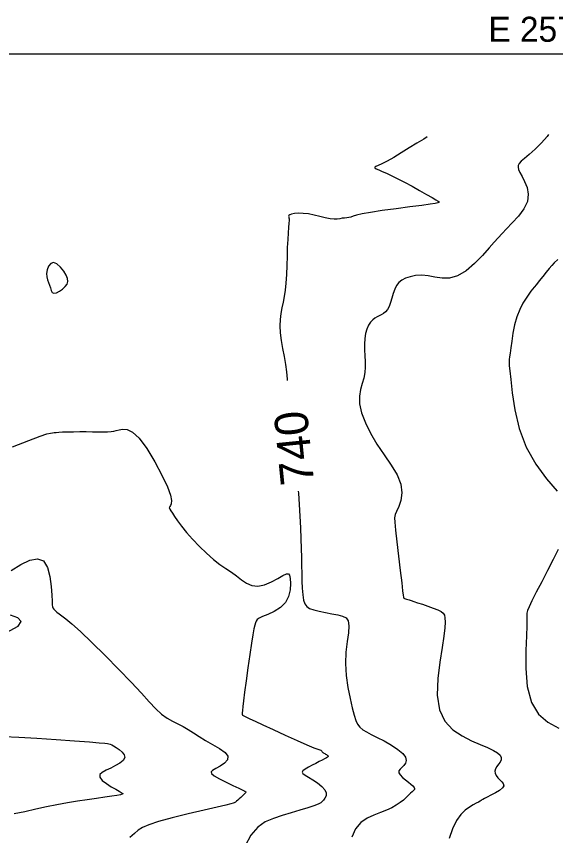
# Model space of a CAD drawing. Extents: x 2566142 to 2571431, y 418755 to 421584.
# Drawn here: x 2569642.8 to 2569965.9, y 421093.3 to 421584.4 of the extents above; entities that cross this region are included whole.
import ezdxf

# ---------------------------------------------------------------- set-up
doc = ezdxf.new("R2010")
doc.units = 0
for name, color, linetype in [('Contour_ADS_Label_Major', 7, 'Continuous'), ('Contour_ADS_Major', 7, 'Continuous'), ('Contour_ADS_Minor', 7, 'Continuous'), ('Contour_ADS_State_Plane_Border', 7, 'Continuous')]:
    doc.layers.add(name, color=color, linetype=linetype)

msp = doc.modelspace()

# ---------------------------------------------------------------- linework, layer by layer
at = {"layer": 'Contour_ADS_Major'}
for points in [[(2569889.03, 421512.21), (2569886.89, 421510.88), (2569882.78, 421508.41), (2569878.19, 421505.58), (2569873.45, 421502.62), (2569868.91, 421499.85), (2569864.93, 421497.56), (2569861.8, 421495.98), (2569859.54, 421494.98), (2569858.12, 421494.37), (2569857.49, 421493.95), (2569857.62, 421493.52), (2569858.45, 421493.01), (2569859.93, 421492.35), (2569862, 421491.47), (2569864.61, 421490.31), (2569867.74, 421488.85), (2569871.35, 421487.08), (2569875.43, 421484.97), (2569879.88, 421482.55), (2569884.36, 421480.04), (2569888.49, 421477.69), (2569891.87, 421475.77), (2569894.2, 421474.45), (2569895.55, 421473.65), (2569896.1, 421473.18), (2569896.01, 421472.88), (2569895.35, 421472.6), (2569893.74, 421472.24), (2569890.69, 421471.76), (2569885.73, 421471.07), (2569878.64, 421470.15), (2569870.35, 421469.08), (2569862.04, 421467.95), (2569854.92, 421466.88), (2569849.89, 421465.94), (2569846.66, 421465.16), (2569844.63, 421464.55), (2569843.23, 421464.11), (2569841.96, 421463.83), (2569840.7, 421463.66), (2569839.42, 421463.52), (2569838.09, 421463.35), (2569836.67, 421463.1), (2569835.06, 421462.88), (2569833.14, 421462.82), (2569830.78, 421463.05), (2569827.91, 421463.65), (2569824.68, 421464.47), (2569821.27, 421465.32), (2569817.87, 421465.99), (2569814.66, 421466.32), (2569811.79, 421466.36), (2569809.39, 421466.17), (2569807.61, 421465.85), (2569806.54, 421465.46), (2569806.03, 421465.03), (2569805.91, 421464.58), (2569805.99, 421464.15), (2569806.1, 421463.7), (2569806.18, 421463.07), (2569806.2, 421462.04), (2569806.13, 421460.37), (2569805.93, 421457.9), (2569805.66, 421454.63), (2569805.37, 421450.62), (2569805.12, 421445.92), (2569804.95, 421440.64), (2569804.8, 421435.07), (2569804.61, 421429.59), (2569804.31, 421424.55), (2569803.84, 421420.21), (2569803.25, 421416.44), (2569802.59, 421413.02), (2569801.93, 421409.72), (2569801.34, 421406.34), (2569800.9, 421402.78), (2569800.72, 421398.93), (2569800.9, 421394.73), (2569801.48, 421390.13), (2569802.33, 421385.29), (2569803.26, 421380.42), (2569804.08, 421375.71), (2569804.66, 421371.28), (2569805.05, 421366.93), (2569805.11, 421366.09)], [(2569811.67, 421299.75), (2569811.77, 421298.66), (2569812.25, 421291.83), (2569812.64, 421284.77), (2569812.95, 421277.8), (2569813.19, 421271.26), (2569813.39, 421265.39), (2569813.55, 421260.09), (2569813.69, 421255.19), (2569813.8, 421250.49), (2569813.9, 421245.89), (2569814.06, 421241.55), (2569814.34, 421237.68), (2569814.82, 421234.52), (2569815.57, 421232.22), (2569816.74, 421230.63), (2569818.48, 421229.51), (2569820.97, 421228.65), (2569824.25, 421227.85), (2569828.02, 421227.07), (2569831.87, 421226.33), (2569835.39, 421225.61), (2569838.23, 421224.87), (2569840.31, 421223.78), (2569841.59, 421222), (2569842.05, 421219.13), (2569841.73, 421214.93), (2569840.99, 421209.57), (2569840.26, 421203.3), (2569839.96, 421196.42), (2569840.4, 421189.21), (2569841.41, 421182.1), (2569842.72, 421175.52), (2569844.02, 421169.9), (2569845.12, 421165.57), (2569846.12, 421162.37), (2569847.19, 421160.01), (2569848.53, 421158.24), (2569850.29, 421156.77), (2569852.57, 421155.4), (2569855.44, 421153.94), (2569858.97, 421152.19), (2569863.13, 421150.02), (2569867.46, 421147.55), (2569871.4, 421144.99), (2569874.38, 421142.52), (2569875.99, 421140.31), (2569876.41, 421138.37), (2569875.97, 421136.71), (2569874.99, 421135.32), (2569873.8, 421134.17), (2569872.7, 421133.15), (2569871.98, 421132.13), (2569871.91, 421131), (2569872.71, 421129.66), (2569874.14, 421128.18), (2569875.89, 421126.69), (2569877.66, 421125.29), (2569879.16, 421124.08), (2569880.32, 421123.06), (2569881.08, 421122.21), (2569881.42, 421121.5), (2569881.3, 421120.89), (2569880.79, 421120.3), (2569879.97, 421119.61), (2569878.94, 421118.72), (2569877.75, 421117.55), (2569876.36, 421116.15), (2569874.71, 421114.61), (2569872.75, 421113.03), (2569870.41, 421111.48), (2569867.68, 421109.96), (2569864.54, 421108.49), (2569860.98, 421107.05), (2569857.05, 421105.58), (2569853.03, 421103.76), (2569849.25, 421101.18), (2569846.06, 421097.44), (2569843.7, 421092.31)]]:
    msp.add_lwpolyline(points, dxfattribs=at)
msp.add_lwpolyline([(2569665.27, 421418.4), (2569666.79, 421418.67), (2569668.63, 421419.58), (2569670.48, 421420.9), (2569672.06, 421422.4), (2569673.13, 421423.9), (2569673.62, 421425.46), (2569673.47, 421427.23), (2569672.64, 421429.31), (2569671.15, 421431.74), (2569669.22, 421434.13), (2569667.1, 421435.97), (2569665.07, 421436.78), (2569663.35, 421436.23), (2569662.03, 421434.63), (2569661.16, 421432.45), (2569660.79, 421430.18), (2569660.93, 421428.18), (2569661.42, 421426.45), (2569662.08, 421424.84), (2569662.71, 421423.24), (2569663.18, 421421.59), (2569663.62, 421420.06), (2569664.25, 421418.92), (2569665.27, 421418.4)], close=True, dxfattribs=at)
at = {"layer": 'Contour_ADS_Minor'}
for points in [[(2569961.65, 421513.59), (2569960.9, 421512.41), (2569957.45, 421508.56), (2569953.58, 421504.86), (2569949.98, 421501.68), (2569947.22, 421499.29), (2569945.3, 421497.55), (2569944.11, 421496.23), (2569943.51, 421495.09), (2569943.4, 421493.91), (2569943.75, 421492.51), (2569944.54, 421490.73), (2569945.78, 421488.4), (2569947.35, 421485.4), (2569948.79, 421481.82), (2569949.53, 421477.8), (2569949.03, 421473.49), (2569946.91, 421469.03), (2569943.66, 421464.66), (2569939.96, 421460.6), (2569936.51, 421457.1), (2569933.79, 421454.26), (2569931.49, 421451.72), (2569929.09, 421448.99), (2569926.09, 421445.55), (2569922.11, 421441.13), (2569917.39, 421436.33), (2569912.28, 421431.94), (2569907.17, 421428.79), (2569902.36, 421427.42), (2569897.85, 421427.43), (2569893.6, 421428.15), (2569889.55, 421428.91), (2569885.66, 421429.2), (2569882.03, 421428.97), (2569878.77, 421428.33), (2569875.97, 421427.39), (2569873.73, 421426.23), (2569871.97, 421424.8), (2569870.59, 421423.03), (2569869.49, 421420.88), (2569868.58, 421418.31), (2569867.76, 421415.55), (2569866.96, 421412.84), (2569866.08, 421410.46), (2569865.07, 421408.6), (2569863.94, 421407.22), (2569862.73, 421406.2), (2569861.46, 421405.46), (2569860.18, 421404.87), (2569858.89, 421404.29), (2569857.58, 421403.57), (2569856.28, 421402.55), (2569854.98, 421401.12), (2569853.77, 421399.25), (2569852.75, 421396.97), (2569851.99, 421394.28), (2569851.56, 421391.23), (2569851.41, 421387.92), (2569851.44, 421384.46), (2569851.58, 421380.97), (2569851.71, 421377.55), (2569851.74, 421374.2), (2569851.53, 421370.9), (2569850.96, 421367.61), (2569850, 421364.3), (2569848.98, 421360.76), (2569848.31, 421356.8), (2569848.43, 421352.2), (2569849.64, 421346.82), (2569851.89, 421340.83), (2569855.01, 421334.47), (2569858.83, 421327.99), (2569863.12, 421321.6), (2569867.34, 421315.4), (2569870.9, 421309.48), (2569873.19, 421303.91), (2569873.82, 421298.79), (2569873.2, 421294.26), (2569871.92, 421290.5), (2569870.6, 421287.66), (2569869.74, 421285.71), (2569869.39, 421283.86), (2569869.49, 421281.12), (2569870, 421276.48), (2569870.82, 421269.35), (2569871.82, 421260.77), (2569872.82, 421252.14), (2569873.66, 421244.88), (2569874.21, 421240.08), (2569874.54, 421237.39), (2569874.78, 421236.16), (2569875.04, 421235.7), (2569875.42, 421235.44), (2569875.93, 421235.25), (2569876.57, 421235.07), (2569877.31, 421234.86), (2569878.19, 421234.59), (2569879.34, 421234.2), (2569880.94, 421233.65), (2569883.15, 421232.9)], [(2569967.18, 421438.64), (2569965.12, 421436.63), (2569963.6, 421435.02), (2569962.1, 421433.29), (2569960.25, 421431.04), (2569958.17, 421428.47), (2569956.13, 421425.93), (2569954.37, 421423.75), (2569953.08, 421422.15), (2569952.07, 421420.89), (2569951.08, 421419.59), (2569949.85, 421417.9), (2569948.21, 421415.5), (2569946.3, 421412.39), (2569944.36, 421408.63), (2569942.62, 421404.28), (2569941.28, 421399.45), (2569940.3, 421394.48), (2569939.58, 421389.77), (2569939.06, 421385.7), (2569938.65, 421382.59), (2569938.35, 421380.32), (2569938.14, 421378.7), (2569938.02, 421377.55), (2569938.01, 421376.56), (2569938.14, 421374.99), (2569938.46, 421372), (2569939.01, 421366.73), (2569939.91, 421358.66), (2569941.49, 421348.52), (2569944.14, 421337.35), (2569948.25, 421326.21), (2569953.98, 421315.99), (2569960.53, 421307.07), (2569966.86, 421299.67)], [(2569640.37, 421326.26), (2569650.3, 421330.17), (2569657.04, 421332.7), (2569661.02, 421334.04), (2569663.16, 421334.6), (2569664.37, 421334.77), (2569665.43, 421334.89), (2569666.66, 421335.02), (2569668.28, 421335.15), (2569670.49, 421335.26), (2569673.42, 421335.35), (2569676.91, 421335.41), (2569680.71, 421335.45), (2569684.6, 421335.44), (2569688.35, 421335.41), (2569691.83, 421335.37), (2569694.92, 421335.36), (2569697.48, 421335.4), (2569699.48, 421335.52), (2569701.11, 421335.74), (2569702.64, 421336.07), (2569704.34, 421336.51), (2569706.44, 421336.94), (2569709.07, 421336.76), (2569712.31, 421335.19), (2569716.26, 421331.49), (2569720.88, 421325.26), (2569725.67, 421317.45), (2569730.02, 421309.36), (2569733.32, 421302.31), (2569735.12, 421297.28), (2569735.71, 421294.09), (2569735.54, 421292.22), (2569735.09, 421291.18), (2569734.72, 421290.54), (2569734.51, 421290.13), (2569734.42, 421289.87), (2569734.44, 421289.64), (2569734.55, 421289.37), (2569734.82, 421288.88), (2569735.36, 421288.03), (2569736.24, 421286.65), (2569737.56, 421284.62), (2569739.38, 421281.96), (2569741.76, 421278.74), (2569744.76, 421275.03), (2569748.39, 421270.92), (2569752.44, 421266.66), (2569756.67, 421262.55), (2569760.82, 421258.89), (2569764.69, 421255.88), (2569768.27, 421253.37), (2569771.6, 421251.14), (2569774.74, 421248.95), (2569777.74, 421246.69), (2569780.75, 421244.64), (2569783.95, 421243.21), (2569787.51, 421242.81), (2569791.5, 421243.67), (2569795.6, 421245.39), (2569799.41, 421247.41), (2569802.5, 421249.16), (2569804.59, 421250.16), (2569805.83, 421250.25), (2569806.47, 421249.35), (2569806.79, 421247.37), (2569806.96, 421244.32), (2569806.76, 421240.59), (2569805.87, 421236.66), (2569803.99, 421233.01), (2569800.96, 421230.01), (2569797.25, 421227.66), (2569793.5, 421225.87), (2569790.35, 421224.54), (2569788.27, 421223.56), (2569787.09, 421222.75), (2569786.48, 421221.92), (2569786.11, 421220.89), (2569785.69, 421219.42), (2569785.16, 421217.16), (2569784.48, 421213.69), (2569783.63, 421208.63), (2569782.6, 421201.79), (2569781.5, 421193.95), (2569780.45, 421186.1), (2569779.55, 421179.23)], [(2569967.39, 421264.86), (2569964.48, 421258.77), (2569961.1, 421252.11), (2569957.58, 421245.37), (2569954.32, 421239.16), (2569951.69, 421234.04), (2569949.99, 421230.46), (2569949.07, 421228.14), (2569948.71, 421226.68), (2569948.65, 421225.64), (2569948.68, 421224.55), (2569948.7, 421222.65), (2569948.64, 421219.1), (2569948.41, 421213.09), (2569948.06, 421204.18), (2569948.05, 421193.52), (2569948.95, 421182.65), (2569951.35, 421173.12), (2569955.61, 421166.08), (2569961.29, 421161.19), (2569967.77, 421157.69)], [(2569639.57, 421252.3), (2569645.49, 421255.86), (2569650.85, 421258.39), (2569655.42, 421259.28), (2569658.99, 421257.95), (2569661.42, 421254.07), (2569662.9, 421248.55), (2569663.68, 421242.57), (2569664.04, 421237.35), (2569664.2, 421233.78), (2569664.3, 421231.66), (2569664.44, 421230.48), (2569664.72, 421229.74), (2569665.24, 421229.02), (2569666.02, 421228.22), (2569667.06, 421227.33)], [(2569883.15, 421232.9), (2569886.04, 421231.93), (2569889.3, 421230.81), (2569892.52, 421229.67), (2569895.28, 421228.6), (2569897.27, 421227.66), (2569898.55, 421226.68), (2569899.28, 421225.45), (2569899.61, 421223.75), (2569899.67, 421221.32), (2569899.42, 421217.81), (2569898.83, 421212.85), (2569897.82, 421206.06), (2569896.46, 421197.31), (2569895.3, 421187.44), (2569895.02, 421177.56), (2569896.28, 421168.76), (2569899.53, 421161.89), (2569904.28, 421156.78), (2569909.83, 421153.02), (2569915.48, 421150.18), (2569920.62, 421147.9), (2569925.03, 421146.01), (2569928.58, 421144.39), (2569931.15, 421142.93), (2569932.67, 421141.52), (2569933.29, 421140.13), (2569933.19, 421138.76), (2569932.58, 421137.4), (2569931.65, 421136.05), (2569930.65, 421134.7), (2569929.82, 421133.34), (2569929.42, 421131.99), (2569929.61, 421130.63), (2569930.31, 421129.29), (2569931.34, 421127.99), (2569932.53, 421126.76), (2569933.71, 421125.58), (2569934.57, 421124.43), (2569934.81, 421123.22), (2569934.12, 421121.88), (2569932.31, 421120.39), (2569929.8, 421118.87), (2569927.11, 421117.45), (2569924.8, 421116.29), (2569923.26, 421115.5), (2569922.35, 421114.99), (2569921.78, 421114.64), (2569921.28, 421114.33), (2569920.6, 421113.95), (2569919.63, 421113.42), (2569918.3, 421112.7), (2569916.53, 421111.73), (2569914.29, 421110.43), (2569911.74, 421108.59), (2569909.07, 421105.95), (2569906.48, 421102.29), (2569904.14, 421097.44), (2569902.05, 421091.58)], [(2569667.06, 421227.33), (2569668.38, 421226.33), (2569670.07, 421225.11), (2569672.47, 421223.26), (2569676.01, 421220.26), (2569681.13, 421215.61), (2569688.04, 421209.02), (2569696.03, 421201.17), (2569704.21, 421192.93), (2569711.65, 421185.19), (2569717.66, 421178.68), (2569722.42, 421173.42), (2569726.33, 421169.27), (2569729.8, 421166.09), (2569733.14, 421163.71), (2569736.42, 421161.88), (2569739.62, 421160.3), (2569742.74, 421158.72), (2569745.79, 421156.89), (2569748.92, 421154.83), (2569752.3, 421152.6), (2569756.11, 421150.27), (2569760.36, 421147.9), (2569764.5, 421145.53), (2569767.81, 421143.18), (2569769.55, 421140.9), (2569769.27, 421138.71), (2569767.47, 421136.7), (2569764.9, 421134.94), (2569762.31, 421133.5), (2569760.38, 421132.41), (2569759.42, 421131.49), (2569759.64, 421130.48), (2569761.29, 421129.16), (2569764.41, 421127.37), (2569768.43, 421125.31), (2569772.57, 421123.3), (2569776.08, 421121.63), (2569778.39, 421120.53), (2569779.65, 421119.91), (2569780.19, 421119.62), (2569780.34, 421119.49), (2569780.36, 421119.39), (2569780.28, 421119.24), (2569780.06, 421118.97), (2569779.63, 421118.53), (2569778.99, 421117.88), (2569778.18, 421117.07), (2569777.28, 421116.2), (2569776.36, 421115.34), (2569775.5, 421114.57), (2569774.71, 421113.92), (2569773.99, 421113.38), (2569773.34, 421112.97), (2569772.65, 421112.67), (2569771.25, 421112.28), (2569768.34, 421111.6), (2569763.14, 421110.41), (2569755.24, 421108.57), (2569745.74, 421106.3), (2569736.13, 421103.9), (2569727.9, 421101.66), (2569722.15, 421099.8), (2569718.4, 421098.16), (2569715.81, 421096.5), (2569713.5, 421094.58), (2569710.81, 421092.23)], [(2569636.83, 421215.01), (2569643.76, 421218.79), (2569645.72, 421221.72), (2569643.66, 421223.89), (2569639.17, 421225.47)], [(2569779.55, 421179.23), (2569778.91, 421174.12), (2569778.5, 421170.61), (2569778.27, 421168.35), (2569778.17, 421166.96), (2569778.16, 421166.1), (2569778.32, 421165.57), (2569778.73, 421165.2), (2569779.47, 421164.82), (2569780.67, 421164.25), (2569782.65, 421163.33), (2569785.79, 421161.88), (2569790.44, 421159.73), (2569796.74, 421156.81), (2569803.93, 421153.51), (2569810.98, 421150.3), (2569816.9, 421147.68), (2569820.94, 421145.99), (2569823.33, 421145.08), (2569824.58, 421144.66), (2569825.17, 421144.44), (2569825.53, 421144.19), (2569825.79, 421143.88), (2569825.99, 421143.57), (2569826.18, 421143.28), (2569826.42, 421143.05), (2569826.72, 421142.85), (2569827.08, 421142.66), (2569827.53, 421142.43), (2569828.06, 421142.16), (2569828.6, 421141.85), (2569829.1, 421141.52), (2569829.48, 421141.21), (2569829.67, 421140.92), (2569829.61, 421140.63), (2569829.27, 421140.27), (2569828.57, 421139.82), (2569827.49, 421139.24), (2569826.06, 421138.5), (2569824.29, 421137.62), (2569822.24, 421136.6), (2569819.96, 421135.44), (2569817.73, 421134.24), (2569815.82, 421133.08), (2569814.52, 421132.06), (2569814.08, 421131.23), (2569814.5, 421130.46), (2569815.74, 421129.58), (2569817.73, 421128.39), (2569820.36, 421126.79), (2569823.22, 421124.87), (2569825.83, 421122.8), (2569827.68, 421120.76), (2569828.44, 421118.87), (2569828.33, 421117.2), (2569827.68, 421115.77), (2569826.86, 421114.6), (2569826.09, 421113.69), (2569825.12, 421112.92), (2569823.57, 421112.14), (2569821.06, 421111.19), (2569817.35, 421109.97), (2569812.69, 421108.51), (2569807.47, 421106.93), (2569802.06, 421105.3), (2569796.82, 421103.61), (2569791.89, 421101.44), (2569787.37, 421098.27), (2569783.36, 421093.57), (2569779.91, 421087.06)], [(2569635.26, 421152.76), (2569644.17, 421152.35), (2569654.98, 421151.69), (2569666.6, 421150.9), (2569677.6, 421150.1), (2569686.56, 421149.42), (2569692.45, 421148.96), (2569695.77, 421148.68), (2569697.4, 421148.49), (2569698.21, 421148.3), (2569698.97, 421148.05), (2569699.88, 421147.65), (2569701.03, 421147.04), (2569702.52, 421146.13), (2569704.33, 421144.89), (2569706.1, 421143.4), (2569707.38, 421141.74), (2569707.71, 421140.03), (2569706.79, 421138.36), (2569704.83, 421136.75), (2569702.22, 421135.23), (2569699.33, 421133.81), (2569696.53, 421132.5), (2569694.22, 421131.21), (2569692.82, 421129.83), (2569692.73, 421128.24), (2569692.73, 421128.24)], [(2569692.73, 421128.24), (2569694.18, 421126.4), (2569696.7, 421124.44), (2569699.64, 421122.59), (2569702.34, 421121.03), (2569704.29, 421119.93), (2569705.54, 421119.22), (2569706.24, 421118.78), (2569706.57, 421118.5), (2569706.63, 421118.27), (2569706.23, 421118.04), (2569705.13, 421117.75), (2569703.07, 421117.37), (2569699.89, 421116.87), (2569695.71, 421116.25), (2569690.77, 421115.53), (2569685.28, 421114.74), (2569679.45, 421113.87), (2569673.37, 421112.91), (2569667.11, 421111.8), (2569660.77, 421110.53), (2569654.39, 421109.07), (2569647.94, 421107.58), (2569641.38, 421106.24)]]:
    msp.add_lwpolyline(points, dxfattribs=at)
at = {"layer": 'Contour_ADS_State_Plane_Border'}
msp.add_lwpolyline([(2566164.43, 418777.5), (2571407.81, 418777.5), (2571407.81, 421561.67), (2566164.43, 421561.67), (2566164.43, 418777.5)], close=True, dxfattribs=at)

# ---------------------------------------------------------------- texts
at = {"layer": 'Contour_ADS_Label_Major'}
msp.add_text('740', height=20, rotation=95.6527, dxfattribs=at).set_placement((2569821.27, 421304.33))
at = {"layer": 'Contour_ADS_State_Plane_Border'}
msp.add_text(' E 2570000', height=15, dxfattribs=at).set_placement((2569920, 421569.17))

doc.saveas('drawing.dxf')
